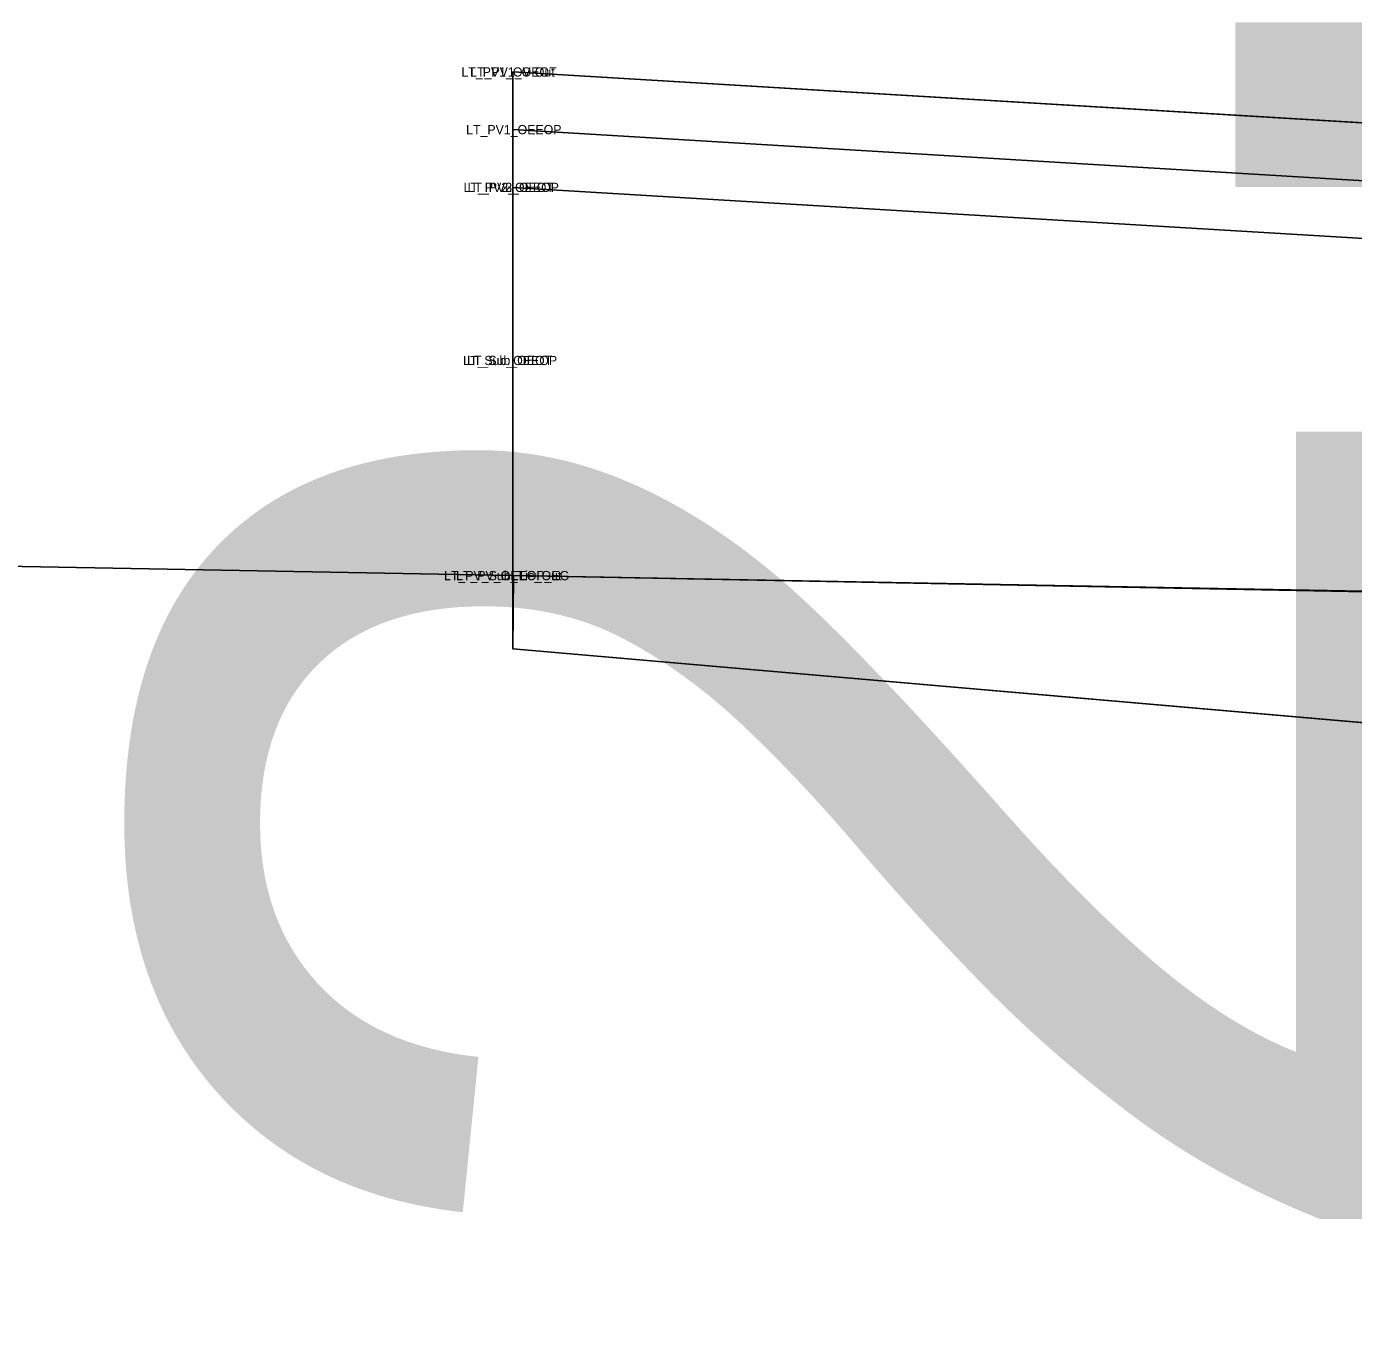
# Model space of a CAD drawing. Extents: x -516 to 303, y -10 to 5017.
# Drawn here: x 146.947 to 149.821, y 2504.105 to 2506.928 of the extents above; entities that cross this region are included whole.
import ezdxf

# ---------------------------------------------------------------- set-up
doc = ezdxf.new("R2010")
doc.units = 0
for name, color, linetype in [('Exist CMT Pavement', 7, 'Continuous'), ('Exist Cross Section Cell', 7, 'Continuous'), ('Exist XS Ground Line', 7, 'Continuous'), ('Prop CMT Pvmt Course 1', 7, 'Continuous'), ('Prop CMT Pvmt Course 1 Wedge', 7, 'Continuous'), ('Prop CMT Pvmt Course 2', 7, 'Continuous'), ('Prop CMT Pvmt Course 2 Wedge', 7, 'Continuous'), ('Prop CMT Pvmt Course 3', 7, 'Continuous'), ('Prop CMT Pvmt Course 3 Wedge', 7, 'Continuous'), ('Prop CMT Pvmt Surface', 7, 'Continuous'), ('Prop CMT Subgrade Earthwork', 7, 'Continuous'), ('Prop Road Sect_ Misc - Drafting Aid (solid line)', 7, 'Continuous'), ('Prop Road Sect_ Recs - UC Shallow (Outline)', 7, 'Continuous'), ('Prop Road Sect_ Recs - UC Shallow (Pattern)', 7, 'Continuous'), ('Scratch_Level_0', 7, 'Continuous')]:
    doc.layers.add(name, color=color, linetype=linetype)

msp = doc.modelspace()

# ---------------------------------------------------------------- linework, layer by layer
at = {"layer": 'Exist CMT Pavement'}
msp.add_lwpolyline([(149.9985, 2505.7005), (148.0015, 2505.7383)], dxfattribs=at)
at = {"layer": 'Exist XS Ground Line'}
msp.add_lwpolyline([(131.6756, 2506.039), (149.0951, 2505.7181), (150.1702, 2505.6981), (151.2449, 2505.6798), (153.9281, 2505.658), (155.8468, 2505.6298), (156.5413, 2505.6134), (157.7961, 2505.5833), (159.1952, 2505.5519), (159.7504, 2505.5399), (161.3095, 2505.5036), (161.8359, 2505.4913), (163.6405, 2505.4476), (164.4857, 2505.426), (165.5232, 2505.4046), (166.0583, 2505.3912), (166.8223, 2505.373), (167.2292, 2505.3687), (168.2607, 2505.3287)], dxfattribs=at)
at = {"layer": 'Prop CMT Pvmt Course 1'}
for points in [[(148, 2506.8294), (148, 2506.8294), (148, 2506.5794), (148, 2506.5793), (148, 2506.7044)], [(148, 2506.7044), (148, 2506.8294)], [(150, 2506.7094), (148, 2506.8294)], [(148, 2506.8294), (148, 2506.7044)], [(148, 2506.7044), (150, 2506.5844)]]:
    msp.add_lwpolyline(points, dxfattribs=at)
at = {"layer": 'Prop CMT Pvmt Course 1 Wedge'}
msp.add_lwpolyline([(150, 2506.5844), (148, 2506.7044)], dxfattribs=at)
at = {"layer": 'Prop CMT Pvmt Course 2'}
msp.add_lwpolyline([(148, 2506.5794), (148, 2506.5793), (148, 2506.5793)], close=True, dxfattribs=at)
msp.add_lwpolyline([(148, 2506.5794), (148, 2506.5794)], dxfattribs=at)
at = {"layer": 'Prop CMT Pvmt Course 2 Wedge'}
msp.add_lwpolyline([(150, 2506.4593), (148, 2506.5793)], dxfattribs=at)
at = {"layer": 'Prop CMT Pvmt Course 3'}
for points in [[(148, 2506.5793), (148, 2506.5794), (148, 2506.2044), (148, 2506.2043)], [(148, 2506.2043), (148, 2506.5793)]]:
    msp.add_lwpolyline(points, dxfattribs=at)
at = {"layer": 'Prop CMT Pvmt Course 3 Wedge'}
msp.add_lwpolyline([(150, 2506.4593), (148, 2506.5793)], dxfattribs=at)
at = {"layer": 'Prop CMT Pvmt Surface'}
for p, q in [((148, 2506.8294), (148, 2505.7383)), ((150, 2506.7094), (148, 2506.8294)), ((148, 2506.8294), (148, 2506.8294))]:
    msp.add_line(p, q, dxfattribs=at)
at = {"layer": 'Prop CMT Subgrade Earthwork'}
msp.add_line((148, 2506.2043), (148, 2506.2044), dxfattribs=at)
at = {"layer": 'Prop Road Sect_ Misc - Drafting Aid (solid line)'}
for p, q in [((148, 2506.5794), (148, 2505.5794)), ((148, 2505.5794), (162, 2504.3643))]:
    msp.add_line(p, q, dxfattribs=at)
at = {"layer": 'Prop Road Sect_ Recs - UC Shallow (Outline)'}
msp.add_lwpolyline([(165.6649, 2504.2045), (165.6649, 2505.2045), (165.6649, 2505.401), (165.5232, 2505.4046), (164.4857, 2505.426), (163.6405, 2505.4476), (161.8359, 2505.4913), (159.7504, 2505.5399), (159.1952, 2505.5519), (157.7961, 2505.5833), (156.5413, 2505.6134), (155.8468, 2505.6298), (153.9281, 2505.658), (151.2449, 2505.6798), (150, 2505.7013), (149.0951, 2505.7181), (148.0015, 2505.7383), (148, 2505.5794), (162, 2504.3643), (164.6649, 2504.2045)], close=True, dxfattribs=at)
at = {"layer": 'Prop Road Sect_ Recs - UC Shallow (Pattern)'}
msp.add_lwpolyline([(165.6649, 2504.2045), (165.6649, 2505.2045), (165.6649, 2505.401), (165.5232, 2505.4046), (164.4857, 2505.426), (163.6405, 2505.4476), (161.8359, 2505.4913), (159.7504, 2505.5399), (159.1952, 2505.5519), (157.7961, 2505.5833), (156.5413, 2505.6134), (155.8468, 2505.6298), (153.9281, 2505.658), (151.2449, 2505.6798), (150, 2505.7013), (149.0951, 2505.7181), (148.0015, 2505.7383), (148, 2505.5794), (162, 2504.3643), (164.6649, 2504.2045), (165.6649, 2504.2045)], dxfattribs=at)

# ---------------------------------------------------------------- texts
at = {"layer": 'Exist Cross Section Cell'}
msp.add_text('N 511412.9707', height=2.8, rotation=90, dxfattribs=at).set_placement((150, 2490))
at = {"layer": 'Scratch_Level_0'}
for s, p in [('LT_PV1_OV-Out', (147.8885, 2506.8194)), ('LT_PV1_OEOT', (147.9074, 2506.8194)), ('LT_PV1_OEEOP', (147.8987, 2506.6944)), ('LT_PV2_OEEOP', (147.8931, 2506.5693)), ('LT_PV3_OEEOP', (147.8931, 2506.5693)), ('LT_PV3_OEOT', (147.9017, 2506.5694)), ('LT_PV2_OEOT', (147.9017, 2506.5694)), ('LT_Sub_OEEOP', (147.8921, 2506.1943)), ('LT_Sub_OEOT', (147.9008, 2506.1944)), ('LT_PV_Sub_Tie_Out', (147.8509, 2505.7283)), ('LT_PV_OEEOP_EG', (147.8769, 2505.7283))]:
    msp.add_text(s, height=0.02, dxfattribs=at).set_placement(p)

doc.saveas('drawing.dxf')
